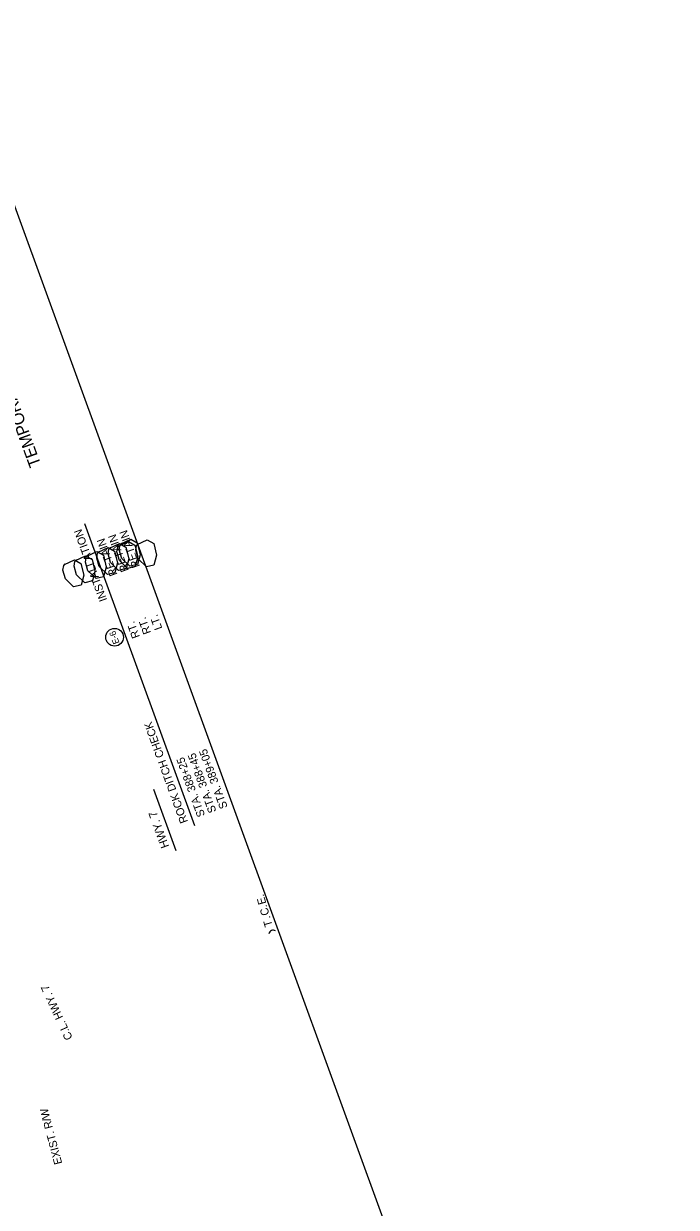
# Model space of a CAD drawing. Extents: x 960650 to 962115, y 1906452 to 1908757.
# Drawn here: x 961626 to 962115, y 1907870 to 1908757 of the extents above; entities that cross this region are included whole.
import ezdxf

# ---------------------------------------------------------------- set-up
doc = ezdxf.new("R2010")
doc.units = 0
for name, color, linetype in [('1', 7, 'Continuous'), ('44', 7, 'Continuous'), ('60', 7, 'Continuous'), ('NO PLOT', 7, 'Continuous'), ('R_Draft', 7, 'Continuous'), ('S_TREE', 7, 'Continuous')]:
    doc.layers.add(name, color=color, linetype=linetype)

msp = doc.modelspace()

# ---------------------------------------------------------------- linework, layer by layer
at = {"layer": '1'}
msp.add_circle((961693.64, 1908296.99), 6.61, dxfattribs=at)
at = {"layer": '44'}
for p, q in [((961753.87, 1908155.56), (961671.44, 1908382.04)), ((961739.8, 1908136.94), (961723.09, 1908182.84))]:
    msp.add_line(p, q, dxfattribs=at)
at = {"layer": 'NO PLOT'}
msp.add_lwpolyline([(962114.55, 1907257.7), (961568.91, 1908756.85), (961079.18, 1908578.6), (961182.12, 1908295.76), (961245.55, 1908318.85), (961390.91, 1907919.48), (961327.48, 1907896.39), (961425.36, 1907627.47), (961483.4, 1907648.6), (961600.59, 1907326.6), (961542.56, 1907305.48), (961624.82, 1907079.46)], close=True, dxfattribs=at)
msp.add_lwpolyline([(962114.55, 1907257.7), (961568.91, 1908756.85), (961079.18, 1908578.6), (961182.12, 1908295.76), (961245.55, 1908318.85), (961390.91, 1907919.48), (961327.48, 1907896.39), (961425.36, 1907627.47), (961483.4, 1907648.6), (961600.59, 1907326.6), (961542.56, 1907305.48), (961624.82, 1907079.46)], close=True, dxfattribs=at)
msp.add_lwpolyline([(962114.55, 1907257.7), (961568.91, 1908756.85), (961079.18, 1908578.6), (961182.12, 1908295.76), (961245.55, 1908318.85), (961390.91, 1907919.48), (961327.48, 1907896.39), (961425.36, 1907627.47), (961483.4, 1907648.6), (961600.59, 1907326.6), (961542.56, 1907305.48), (961624.82, 1907079.46)], close=True, dxfattribs=at)
msp.add_lwpolyline([(962114.55, 1907257.7), (961568.91, 1908756.85), (961079.18, 1908578.6), (961182.12, 1908295.76), (961245.55, 1908318.85), (961390.91, 1907919.48), (961327.48, 1907896.39), (961425.36, 1907627.47), (961483.4, 1907648.6), (961600.59, 1907326.6), (961542.56, 1907305.48), (961624.82, 1907079.46)], close=True, dxfattribs=at)
msp.add_lwpolyline([(962114.55, 1907257.7), (961568.91, 1908756.85), (961079.18, 1908578.6), (961182.12, 1908295.76), (961245.55, 1908318.85), (961390.91, 1907919.48), (961327.48, 1907896.39), (961425.36, 1907627.47), (961483.4, 1907648.6), (961600.59, 1907326.6), (961542.56, 1907305.48), (961624.82, 1907079.46)], close=True, dxfattribs=at)
at = {"layer": 'S_TREE'}
for points in [[(961689.86, 1908363.84), (961697.33, 1908367.33), (961702.16, 1908364.59), (961704.31, 1908355.77), (961702.37, 1908348.39), (961696.67, 1908347.11), (961690.59, 1908353), (961688.73, 1908359.44), (961689.34, 1908363.1), (961690.54, 1908364.32)], [(961689.86, 1908363.84), (961697.33, 1908367.33), (961702.16, 1908364.59), (961704.31, 1908355.77), (961702.37, 1908348.39), (961696.67, 1908347.11), (961690.59, 1908353), (961688.73, 1908359.44), (961689.34, 1908363.1), (961690.54, 1908364.32)], [(961696.51, 1908365.35), (961703.98, 1908368.83), (961708.81, 1908366.1), (961710.96, 1908357.27), (961709.02, 1908349.89), (961703.32, 1908348.62), (961697.24, 1908354.5), (961695.38, 1908360.95), (961695.99, 1908364.6), (961697.19, 1908365.82)], [(961698.31, 1908366.92), (961705.79, 1908370.41), (961710.62, 1908367.67), (961712.76, 1908358.85), (961710.83, 1908351.46), (961705.13, 1908350.19), (961699.05, 1908356.08), (961697.19, 1908362.52), (961697.8, 1908366.18), (961699, 1908367.4)], [(961710.62, 1908366.55), (961718.1, 1908370.03), (961722.93, 1908367.3), (961725.07, 1908358.47), (961723.14, 1908351.09), (961717.44, 1908349.82), (961711.36, 1908355.7), (961709.5, 1908362.15), (961710.11, 1908365.8), (961711.31, 1908367.02)], [(961672.94, 1908357.69), (961680.41, 1908361.17), (961685.24, 1908358.44), (961687.39, 1908349.61), (961685.46, 1908342.23), (961679.75, 1908340.96), (961673.67, 1908346.84), (961671.82, 1908353.29), (961672.43, 1908356.94), (961673.62, 1908358.16)], [(961672.94, 1908357.69), (961680.41, 1908361.17), (961685.24, 1908358.44), (961687.39, 1908349.61), (961685.46, 1908342.23), (961679.75, 1908340.96), (961673.67, 1908346.84), (961671.82, 1908353.29), (961672.43, 1908356.94), (961673.62, 1908358.16)], [(961672.94, 1908357.69), (961680.41, 1908361.17), (961685.24, 1908358.44), (961687.39, 1908349.61), (961685.46, 1908342.23), (961679.75, 1908340.96), (961673.67, 1908346.84), (961671.82, 1908353.29), (961672.43, 1908356.94), (961673.62, 1908358.16)], [(961672.94, 1908357.69), (961680.41, 1908361.17), (961685.24, 1908358.44), (961687.39, 1908349.61), (961685.46, 1908342.23), (961679.75, 1908340.96), (961673.67, 1908346.84), (961671.82, 1908353.29), (961672.43, 1908356.94), (961673.62, 1908358.16)], [(961672.94, 1908357.69), (961680.41, 1908361.17), (961685.24, 1908358.44), (961687.39, 1908349.61), (961685.46, 1908342.23), (961679.75, 1908340.96), (961673.67, 1908346.84), (961671.82, 1908353.29), (961672.43, 1908356.94), (961673.62, 1908358.16)], [(961681.4, 1908360.76), (961688.87, 1908364.25), (961693.7, 1908361.52), (961695.85, 1908352.69), (961693.92, 1908345.31), (961688.21, 1908344.03), (961682.13, 1908349.92), (961680.27, 1908356.36), (961680.89, 1908360.02), (961682.08, 1908361.24)], [(961656.03, 1908351.53), (961663.5, 1908355.02), (961668.33, 1908352.28), (961670.48, 1908343.45), (961668.54, 1908336.07), (961662.84, 1908334.8), (961656.76, 1908340.68), (961654.9, 1908347.13), (961655.52, 1908350.78), (961656.71, 1908352.01)], [(961656.03, 1908351.53), (961663.5, 1908355.02), (961668.33, 1908352.28), (961670.48, 1908343.45), (961668.54, 1908336.07), (961662.84, 1908334.8), (961656.76, 1908340.68), (961654.9, 1908347.13), (961655.52, 1908350.78), (961656.71, 1908352.01)], [(961656.03, 1908351.53), (961663.5, 1908355.02), (961668.33, 1908352.28), (961670.48, 1908343.45), (961668.54, 1908336.07), (961662.84, 1908334.8), (961656.76, 1908340.68), (961654.9, 1908347.13), (961655.52, 1908350.78), (961656.71, 1908352.01)], [(961664.48, 1908354.61), (961671.96, 1908358.09), (961676.79, 1908355.36), (961678.94, 1908346.53), (961677, 1908339.15), (961671.3, 1908337.88), (961665.22, 1908343.76), (961663.36, 1908350.21), (961663.97, 1908353.86), (961665.17, 1908355.08)], [(961664.48, 1908354.61), (961671.96, 1908358.09), (961676.79, 1908355.36), (961678.94, 1908346.53), (961677, 1908339.15), (961671.3, 1908337.88), (961665.22, 1908343.76), (961663.36, 1908350.21), (961663.97, 1908353.86), (961665.17, 1908355.08)], [(961664.48, 1908354.61), (961671.96, 1908358.09), (961676.79, 1908355.36), (961678.94, 1908346.53), (961677, 1908339.15), (961671.3, 1908337.88), (961665.22, 1908343.76), (961663.36, 1908350.21), (961663.97, 1908353.86), (961665.17, 1908355.08)], [(961664.48, 1908354.61), (961671.96, 1908358.09), (961676.79, 1908355.36), (961678.94, 1908346.53), (961677, 1908339.15), (961671.3, 1908337.88), (961665.22, 1908343.76), (961663.36, 1908350.21), (961663.97, 1908353.86), (961665.17, 1908355.08)], [(961664.48, 1908354.61), (961671.96, 1908358.09), (961676.79, 1908355.36), (961678.94, 1908346.53), (961677, 1908339.15), (961671.3, 1908337.88), (961665.22, 1908343.76), (961663.36, 1908350.21), (961663.97, 1908353.86), (961665.17, 1908355.08)]]:
    msp.add_lwpolyline(points, dxfattribs=at)
msp.add_arc((961812.68, 1908073.74), 3.64, 63.338, 164.93491, dxfattribs=at)

# ---------------------------------------------------------------- texts
at = {"layer": '1'}
msp.add_text('E-6 ', height=4.8, rotation=110, dxfattribs=at).set_placement((961697.38, 1908292.82))
at = {"layer": '44'}
for s, height, p in [('INSTALLATION', 6, (961688.21, 1908324.97)), ('RETAIN', 6, (961712.76, 1908350.2)), ('RETAIN', 6, (961695.84, 1908344.04)), ('RETAIN', 6, (961704.3, 1908347.12)), ('LT.', 6, (961729.51, 1908303.67)), ('RT.', 6, (961712.65, 1908297.38)), ('RT.', 6, (961721.1, 1908300.46)), ('ROCK DITCH CHECK', 6, (961748.7, 1908158.78)), ('STA. 388+45', 6, (961770, 1908166.54)), ('STA. 389+05', 6, (961778.46, 1908169.62)), ('STA. 388+25', 6, (961761.55, 1908163.46)), ('HWY. 7', 6.25, (961734.59, 1908140.2))]:
    msp.add_text(s, height=height, rotation=110, dxfattribs=at).set_placement(p)
at = {"layer": '60'}
msp.add_text('TEMPORARY EROSION CONTROL DETAILS', height=9, rotation=110, dxfattribs=at).set_placement((961638.71, 1908426.37))
at = {"layer": 'R_Draft'}
for s, rotation, p in [('E', 105.85702, (961807.38, 1908097.54)), ('.', 105.85702, (961805.9, 1908102.72)), ('C', 105.85702, (961809.73, 1908089.27)), ('.', 105.85702, (961808.18, 1908094.73)), ('T', 105.85702, (961812.13, 1908080.82)), ('.', 105.85702, (961810.53, 1908086.45)), ('C.L. HWY. 7', 114.89566, (961662.37, 1907996.69)), ('EXIST. R/W', 104.76842, (961654.44, 1907902.64))]:
    msp.add_text(s, height=6, rotation=rotation, dxfattribs=at).set_placement(p)

doc.saveas('drawing.dxf')
